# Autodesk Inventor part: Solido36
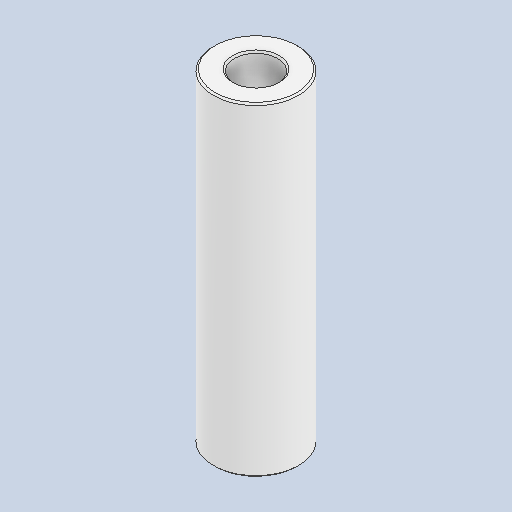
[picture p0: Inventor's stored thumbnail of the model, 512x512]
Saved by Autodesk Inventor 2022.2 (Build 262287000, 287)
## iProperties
Created: 2024-10
Part Number: Solido36
Material: Generico
Document SubType Name: Modeling
Designer: 18907419
Density: 1 g/cm^3
Appearance: Default
Author: 18907419
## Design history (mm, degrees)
feature "Solido36"
node "Solido1"
